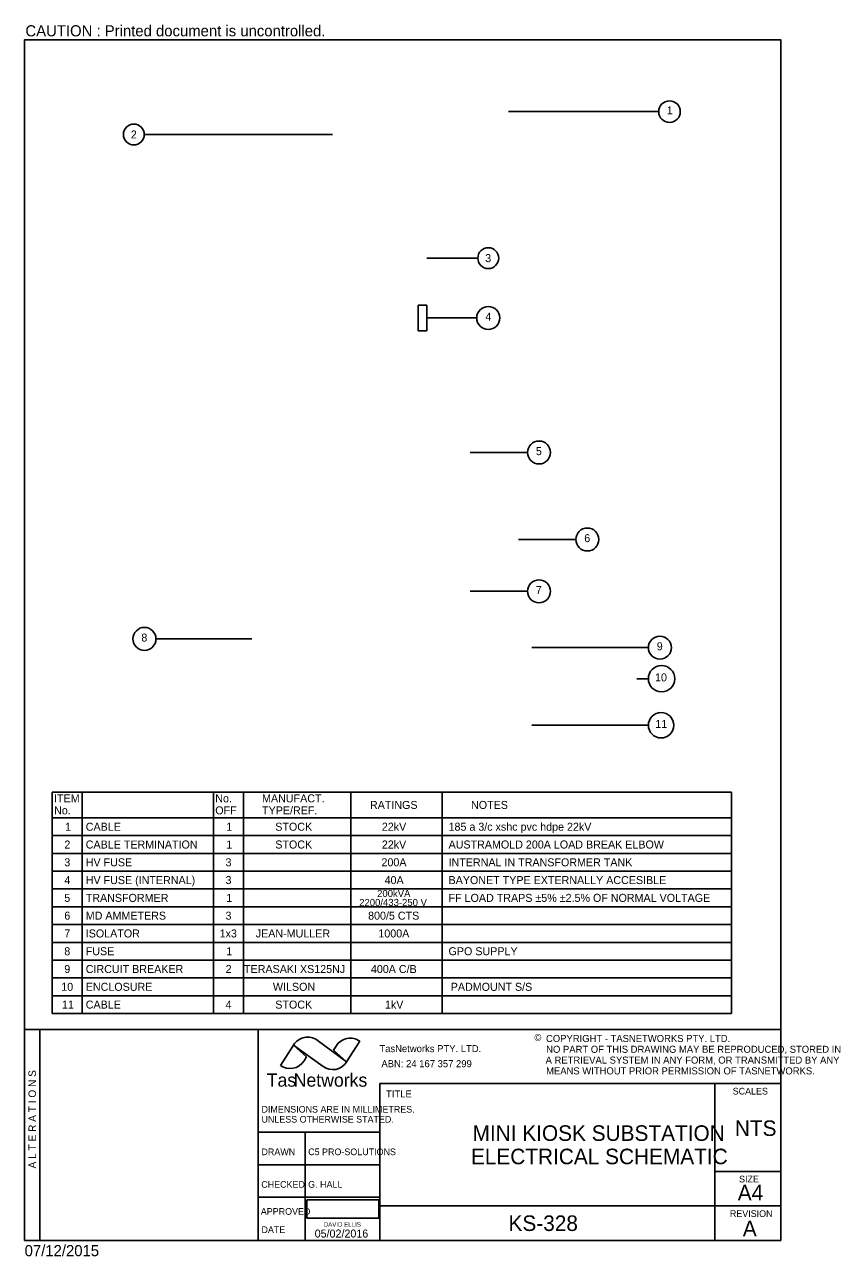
# Model space of a CAD drawing. Extents: x -190 to -7, y 10 to 287.
import ezdxf

# ---------------------------------------------------------------- set-up
doc = ezdxf.new("R2010")
doc.units = 0
doc.layers.add('A4 BORDER TITLE BLOCK', color=7, linetype='Continuous')
doc.layers.add('Default', color=7, linetype='Continuous')

# ---------------------------------------------------------------- blocks, each defined once
blk = doc.blocks.new('POINT_DISPLAY')
at = {"layer": 'Default'}
blk.add_line((0, 0), (0, 0), dxfattribs=at)
blk = doc.blocks.new('David Ellis')
at = {"layer": 'Default'}
blk.add_lwpolyline([(0.38, 5.03), (16.52, 5.03), (16.52, 9.1), (0.38, 9.1)], close=True, dxfattribs=at)
for s, height, p in [('DAVID ELLIS', 1, (4.15, 3.1)), ('05/02/2016', 1.8, (2.12, 0.65))]:
    blk.add_text(s, height=height, dxfattribs=at).set_placement(p)

msp = doc.modelspace()

# ---------------------------------------------------------------- linework, layer by layer
at = {"layer": 'A4 BORDER TITLE BLOCK'}
for p, q in [((-20, 60.93), (-190, 60.93)), ((-186.58, 13.5), (-186.58, 60.93)), ((-137.52, 13.5), (-137.52, 60.93)), ((-117.6, 53.69), (-124.25, 58.52)), ((-117.6, 53.69), (-124.25, 58.52)), ((-117.6, 53.69), (-124.25, 58.52)), ((-117.6, 53.69), (-114.66, 58.29)), ((-117.6, 53.69), (-114.66, 58.29)), ((-117.6, 53.69), (-114.66, 58.29)), ((-129.55, 57.45), (-132.49, 52.85)), ((-129.55, 57.45), (-132.49, 52.85)), ((-129.55, 57.45), (-132.49, 52.85)), ((-129.55, 57.45), (-122.9, 52.62)), ((-129.55, 57.45), (-126.61, 54.82)), ((-126.61, 54.82), (-129.55, 57.45)), ((-129.55, 57.45), (-122.9, 52.62)), ((-129.55, 57.45), (-122.9, 52.62)), ((-129.55, 57.45), (-126.61, 54.82)), ((-119.95, 57.22), (-120.53, 56.32)), ((-119.95, 57.22), (-120.53, 56.32)), ((-119.95, 57.22), (-120.53, 56.32)), ((-120.53, 56.32), (-117.6, 53.69)), ((-120.53, 56.32), (-117.6, 53.69)), ((-120.53, 56.32), (-117.6, 53.69)), ((-127.19, 53.92), (-126.61, 54.82)), ((-127.19, 53.92), (-126.61, 54.82)), ((-127.19, 53.92), (-126.61, 54.82)), ((-110.13, 48.77), (-20, 48.77)), ((-110.13, 48.77), (-110.13, 13.5)), ((-34.83, 13.5), (-34.83, 48.77)), ((-137.52, 37.82), (-110.13, 37.82)), ((-126.91, 37.82), (-126.91, 13.5)), ((-137.52, 30.53), (-110.13, 30.53)), ((-34.83, 29.02), (-20, 29.02)), ((-137.52, 23.23), (-110.13, 23.23)), ((-34.83, 21.26), (-110.13, 21.26)), ((-34.83, 21.26), (-20, 21.26)), ((-20, 13.5), (-190, 13.5))]:
    msp.add_line(p, q, dxfattribs=at)
msp.add_lwpolyline([(-190, 13.5), (-190, 283.5), (-20, 283.5), (-20, 13.5)], dxfattribs=at)
for centre, start_param, end_param in [((-126.39, 55.16), 5.685005, 7.255802), ((-126.39, 55.16), 5.685005, 7.255802), ((-126.39, 55.16), 5.685005, 7.255802), ((-116.8, 54.93), 5.685005, 7.255802), ((-116.8, 54.93), 5.685005, 7.255802), ((-116.8, 54.93), 5.685005, 7.255802), ((-130.34, 56.21), 2.543413, 4.114209), ((-130.34, 56.21), 2.543413, 4.114209), ((-130.34, 56.21), 2.543413, 4.114209), ((-120.75, 55.98), 2.543413, 4.114209), ((-120.75, 55.98), 2.543413, 4.114209), ((-120.75, 55.98), 2.543413, 4.114209)]:
    msp.add_ellipse(centre, major_axis=(0, 4.07), ratio=0.938106, start_param=start_param, end_param=end_param, dxfattribs=at)
at = {"layer": 'Default'}
for p, q in [((-47.45, 267.35), (-81.25, 267.35)), ((-120.76, 262.21), (-163.11, 262.21)), ((-99.56, 234.4), (-88.11, 234.4)), ((-99.56, 223.84), (-101.49, 223.84)), ((-101.49, 223.84), (-101.49, 218.06)), ((-99.56, 218.06), (-99.56, 223.84)), ((-99.56, 220.95), (-88.35, 220.95)), ((-101.49, 218.06), (-99.56, 218.06)), ((-89.86, 190.7), (-76.93, 190.7)), ((-79, 171.13), (-66.07, 171.13)), ((-89.86, 159.48), (-76.93, 159.48)), ((-160.49, 148.78), (-138.89, 148.78)), ((-75.93, 146.81), (-49.76, 146.81)), ((-49.76, 139.83), (-52.35, 139.83)), ((-75.93, 129.35), (-49.76, 129.35)), ((-183.8, 108.54), (-183.8, 114.34)), ((-183.8, 114.34), (-31.11, 114.34)), ((-177.07, 114.34), (-177.07, 64.54)), ((-147.55, 114.34), (-147.55, 64.54)), ((-140.83, 114.34), (-140.83, 64.54)), ((-116.69, 108.54), (-116.69, 114.34)), ((-96.1, 108.54), (-96.1, 114.34)), ((-31.11, 114.34), (-31.11, 64.54)), ((-183.8, 108.54), (-183.8, 64.54)), ((-177.07, 108.54), (-183.8, 108.54)), ((-177.07, 108.54), (-147.55, 108.54)), ((-147.55, 108.54), (-140.83, 108.54)), ((-140.83, 108.54), (-125.4, 108.54)), ((-125.4, 108.54), (-31.11, 108.54)), ((-116.69, 104.54), (-116.69, 108.54)), ((-96.1, 108.54), (-96.1, 64.54)), ((-31.11, 104.54), (-183.8, 104.54)), ((-116.69, 104.54), (-116.69, 64.54)), ((-31.11, 100.54), (-183.8, 100.54)), ((-31.11, 96.54), (-183.8, 96.54)), ((-31.11, 92.54), (-183.8, 92.54)), ((-31.11, 88.54), (-183.8, 88.54)), ((-31.11, 84.54), (-183.8, 84.54)), ((-31.11, 80.54), (-183.8, 80.54)), ((-31.11, 76.54), (-183.8, 76.54)), ((-31.11, 72.54), (-183.8, 72.54)), ((-31.11, 68.54), (-183.8, 68.54)), ((-31.11, 64.54), (-183.8, 64.54))]:
    msp.add_line(p, q, dxfattribs=at)
for centre, radius in [((-45.01, 267.35), 2.43), ((-165.45, 262.21), 2.34), ((-85.76, 234.4), 2.35), ((-85.76, 220.95), 2.59), ((-74.35, 190.7), 2.58), ((-63.49, 171.13), 2.58), ((-74.36, 159.48), 2.57), ((-163.06, 148.78), 2.58), ((-47.18, 146.81), 2.58), ((-46.79, 139.83), 2.97), ((-46.91, 129.35), 2.85)]:
    msp.add_circle(centre, radius, dxfattribs=at)

# ---------------------------------------------------------------- block references
at = {"layer": 'A4 BORDER TITLE BLOCK', "xscale": 1.7000000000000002, "yscale": 1.5882352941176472}
msp.add_blockref('POINT_DISPLAY', (-132.03, 52.53), dxfattribs=at)
msp.add_blockref('POINT_DISPLAY', (-132.03, 52.53), dxfattribs=at)
at = {"layer": 'Default'}
msp.add_blockref('David Ellis', (-126.91, 13.5), dxfattribs=at)

# ---------------------------------------------------------------- texts
at = {"layer": 'A4 BORDER TITLE BLOCK'}
for s, height, p in [('CAUTION : Printed document is uncontrolled.', 2.5, (-189.82, 284.28)), ('©', 1.59, (-75.39, 58.35)), ('COPYRIGHT - TASNETWORKS PTY. LTD.', 1.5882, (-72.78, 58.13)), ('TasNetworks PTY. LTD.', 1.5882, (-110.24, 55.85)), ('NO PART OF THIS DRAWING MAY BE REPRODUCED, STORED IN', 1.5882, (-72.74, 55.7)), ('ABN: 24 167 357 299', 1.5882, (-109.78, 52.46)), ('A RETRIEVAL SYSTEM IN ANY FORM, OR TRANSMITTED BY ANY', 1.5882, (-72.87, 53.27)), ('Tas', 2.97, (-135.57, 48.08)), ('Networks', 2.97, (-129.51, 48.08)), ('MEANS WITHOUT PRIOR PERMISSION OF TASNETWORKS.', 1.5882, (-72.76, 50.84)), ('TITLE', 1.588, (-108.75, 45.66)), ('SCALES', 1.5, (-30.8, 46.32)), ('DIMENSIONS ARE IN MILLIMETRES.', 1.5, (-136.75, 42.25)), ('UNLESS OTHERWISE STATED.', 1.5, (-136.75, 40)), ('MINI KIOSK SUBSTATION', 3.5, (-89.29, 35.89)), ('NTS', 3.5, (-30.32, 37)), ('DRAWN', 1.5, (-136.75, 32.68)), ('C5 PRO-SOLUTIONS', 1.5, (-126.25, 32.68)), ('ELECTRICAL SCHEMATIC', 3.5, (-89.66, 30.64)), ('SIZE', 1.5, (-29.37, 26.55)), ('CHECKED', 1.5, (-136.8, 25.35)), ('G. HALL', 1.5, (-126.25, 25.35)), ('A4 ', 3.5, (-29.67, 22.51)), ('APPROVED', 1.5, (-136.9, 19.27)), ('REVISION', 1.5, (-31.44, 18.79)), ('DATE', 1.5, (-136.75, 15.16)), ('KS-328', 3.5, (-81.21, 15.63)), ('A', 3.5, (-28.53, 14.45)), ('07/12/2015', 2.5, (-190, 9.96))]:
    msp.add_text(s, height=height, dxfattribs=at).set_placement(p)
msp.add_text('A L T E R A T I O N S', height=1.7, rotation=90, dxfattribs=at).set_placement((-187.44, 29.7))
at = {"layer": 'Default'}
for s, height, p in [('1', 1.8, (-45.62, 266.75)), ('2', 1.8, (-166.12, 261.31)), ('3', 1.8, (-86.45, 233.51)), ('4', 1.8, (-86.41, 220.35)), ('5', 1.8, (-75.05, 190.1)), ('6', 1.8, (-64.18, 170.53)), ('7', 1.8, (-75.06, 158.88)), ('8', 1.8, (-163.76, 148.18)), ('9', 1.8, (-47.88, 146.21)), ('10', 1.8, (-48.26, 139.23)), ('11', 1.8, (-48.21, 128.75)), ('ITEM', 1.8, (-183.38, 112.02)), ('No.', 1.8, (-147.14, 112.02)), ('MANUFACT. ', 1.8, (-136.62, 112.02)), ('No.', 1.8, (-183.38, 109.32)), ('OFF', 1.8, (-147.14, 109.32)), ('TYPE/REF.', 1.8, (-136.62, 109.32)), ('RATINGS', 1.8, (-112.36, 110.54)), ('NOTES', 1.8, (-89.63, 110.54)), ('1', 1.8, (-180.9, 105.64)), ('CABLE ', 1.8, (-176.26, 105.64)), ('1', 1.8, (-144.66, 105.64)), ('STOCK', 1.8, (-133.65, 105.64)), ('22kV', 1.8, (-109.69, 105.64)), ('185 a 3/c xshc pvc hdpe 22kV', 1.8, (-94.69, 105.64)), ('2', 1.8, (-181.07, 101.64)), ('CABLE TERMINATION', 1.8, (-176.26, 101.64)), ('1', 1.8, (-144.66, 101.64)), ('STOCK', 1.8, (-133.65, 101.64)), ('22kV', 1.8, (-109.69, 101.64)), ('AUSTRAMOLD 200A LOAD BREAK ELBOW', 1.8, (-94.69, 101.64)), ('3', 1.8, (-181.08, 97.64)), ('HV FUSE', 1.8, (-176.26, 97.64)), ('3', 1.8, (-144.83, 97.64)), ('200A', 1.8, (-109.77, 97.64)), ('INTERNAL IN TRANSFORMER TANK', 1.8, (-94.69, 97.64)), ('4', 1.8, (-181.07, 93.64)), ('HV FUSE (INTERNAL)', 1.8, (-176.26, 93.64)), ('3', 1.8, (-144.83, 93.64)), ('40A', 1.8, (-109.07, 93.64)), ('BAYONET TYPE EXTERNALLY ACCESIBLE', 1.8, (-94.69, 93.64)), ('5', 1.8, (-181.08, 89.64)), ('TRANSFORMER', 1.8, (-176.26, 89.64)), ('1', 1.8, (-144.66, 89.64)), ('200kVA', 1.6, (-110.75, 90.72)), ('FF LOAD TRAPS ±5% ±2.5% OF NORMAL VOLTAGE', 1.8, (-94.69, 89.64)), ('2200/433-250 V', 1.6, (-114.78, 88.71)), ('6', 1.8, (-181.08, 85.64)), ('MD AMMETERS', 1.8, (-176.26, 85.64)), ('3', 1.8, (-144.83, 85.64)), ('800/5 CTS', 1.8, (-112.78, 85.64)), ('7', 1.8, (-181.08, 81.64)), ('ISOLATOR', 1.8, (-176.26, 81.64)), ('1x3', 1.8, (-146.16, 81.64)), ('JEAN-MULLER', 1.8, (-138.04, 81.64)), ('1000A', 1.8, (-110.47, 81.64)), ('8', 1.8, (-181.08, 77.64)), ('FUSE', 1.8, (-176.26, 77.64)), ('1', 1.8, (-144.66, 77.64)), ('GPO SUPPLY', 1.8, (-94.69, 77.64)), ('9', 1.8, (-181.08, 73.64)), ('CIRCUIT BREAKER', 1.8, (-176.26, 73.64)), ('2', 1.8, (-144.82, 73.64)), ('TERASAKI XS125NJ', 1.8, (-140.67, 73.64)), ('400A C/B', 1.8, (-112.15, 73.64)), ('10', 1.8, (-181.77, 69.64)), ('ENCLOSURE', 1.8, (-176.26, 69.64)), ('WILSON', 1.8, (-134.18, 69.64)), ('PADMOUNT S/S', 1.8, (-94.2, 69.64)), ('11', 1.8, (-181.6, 65.64)), ('CABLE', 1.8, (-176.26, 65.64)), ('4', 1.8, (-144.83, 65.64)), ('STOCK', 1.8, (-133.65, 65.64)), ('1kV', 1.8, (-108.99, 65.64))]:
    msp.add_text(s, height=height, dxfattribs=at).set_placement(p)

doc.saveas('drawing.dxf')
